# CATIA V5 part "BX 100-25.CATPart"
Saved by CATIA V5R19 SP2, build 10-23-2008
Part number: BX 100-25
Bounding box of the stored display mesh (mm): x -18.951 to 18.951, y -18.952 to 18.952, z 0 to 135
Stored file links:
  C:\Users\Bora\Desktop\3D Katı model\BX serisi\BX 100\BX 100-25.CATPart
  C:\Program Files\Dassault Systemes\B19\intel_a\reffiles\standard\MetricThickPitch.txt
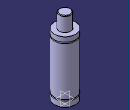
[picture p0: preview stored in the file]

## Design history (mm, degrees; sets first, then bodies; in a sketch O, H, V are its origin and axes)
Body1 (main body)
  Sketch1 on yz-plane, origin (0, 0, 0), H (0, 1, 0), V (0, 0, 1)
    point P2 (19, 9.5)
    line L1 (19, 9.5) -> (19, 0)
    point P3 (19, 9.5)
    point P4 (19, 11.5)
    arc A1 centre (19, 10.5) radius 1 from (19, 11.5) to (19, 9.5) ccw
    point P5 (19, 11.5)
    point P6 (19, 98.5)
    line L2 (19, 98.5) -> (19, 11.5)
    point P7 (19, 98.5)
    point P8 (19, 100.5)
    arc A2 centre (19, 99.5) radius 1 from (19, 100.5) to (19, 98.5) ccw
    point P10 (10, 134)
    arc A3 centre (9, 134) radius 1 from (10, 134) to (9, 135) ccw
    point P12 (10, 134)
    line L3 (10, 134) -> (10, 109)
    point P13 (19, 100.5)
    line L4 (19, 109) -> (19, 100.5)
    line L5 (9, 135) -> (0, 135)
    point P15 (0, 135)
    line L6 (19, 109) -> (10, 109)
    line L7 (19, 0) -> (0, 0)
    tangency: L5 A3
    coincidence: P15 V, P2 P3, P4 P5, P6 P7, P8 P13, P10 P12
    horizontal: L6 H, L7 H
  Shaft1: profile Sketch1, axis Sketch1.V, angle 360
  Sketch2 on face of Shaft1 from Sketch1.L7, origin (0, 0, 0), H (1, 0, 0), V (0, -1, 0)
    point P1 (-9, 0)
    distance P1 V = 9
  Hole1: placed by Sketch2, at (-9, 0, 0) direction (0, 0, 1), diameter 4.917, depth 6, threaded "M6", thread diameter 6, thread depth 6, pitch 1
  Sketch3 on face of Shaft1 from Sketch1.L7, origin (0, 0, 0), H (1, 0, 0), V (0, -1, 0)
    point P1 (9, 0)
    distance P1 V = 9
  Hole2: placed by Sketch3, at (9, 0, 0) direction (0, 0, 1), diameter 4.917, depth 6, threaded "M6", thread diameter 6, thread depth 6, pitch 1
